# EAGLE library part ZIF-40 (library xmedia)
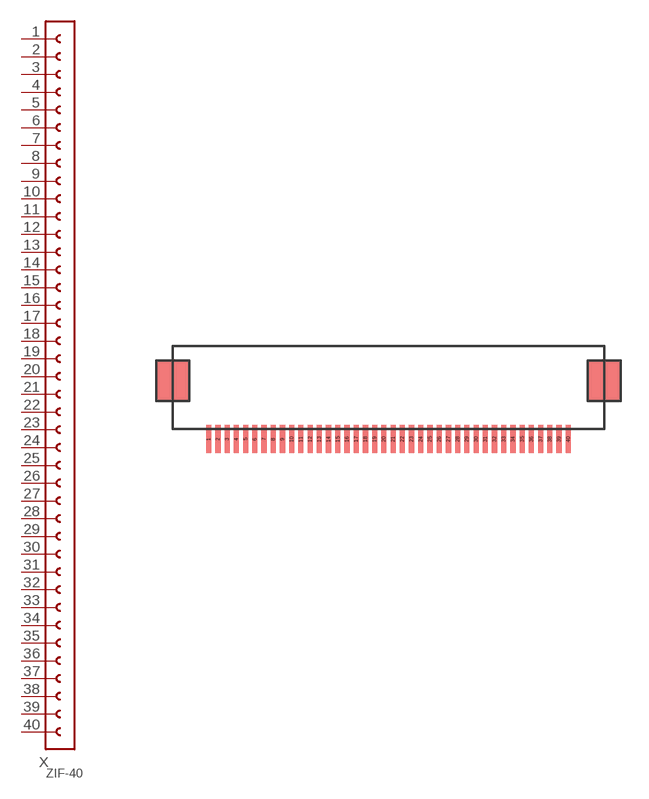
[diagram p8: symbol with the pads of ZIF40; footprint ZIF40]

Designator prefix X

## ZIF-40  [ZIF40]
1  P$1
2  P$2
3  P$3
4  P$4
5  P$5
6  P$6
7  P$7
8  P$8
9  P$9
10  P$10
11  P$11
12  P$12
13  P$13
14  P$14
15  P$15
16  P$16
17  P$17
18  P$18
19  P$19
20  P$20
21  P$21
22  P$22
23  P$23
24  P$24
25  P$25
26  P$26
27  P$27
28  P$28
29  P$29
30  P$30
31  P$31
32  P$32
33  P$33
34  P$34
35  P$35
36  P$36
37  P$37
38  P$38
39  P$39
40  P$40

## Footprint ZIF40 (pad centres in mm)
smd 0.279 x 1.524: 1 0.25,0.75; 2 0.75,0.75; 3 1.25,0.75; 4 1.75,0.75; 5 2.25,0.75; 6 2.75,0.75; 7 3.25,0.75; 8 3.75,0.75; 9 4.25,0.75; 10 4.75,0.75; 11 5.25,0.75; 12 5.75,0.75; 13 6.25,0.75; 14 6.75,0.75; 15 7.25,0.75; 16 7.75,0.75; 17 8.25,0.75; 18 8.75,0.75; 19 9.25,0.75; 20 9.75,0.75; 21 10.25,0.75; 22 10.75,0.75; 23 11.25,0.75; 24 11.75,0.75; 25 12.25,0.75; 26 12.75,0.75; 27 13.25,0.75; 28 13.75,0.75; 29 14.25,0.75; 30 14.75,0.75; 31 15.25,0.75; 32 15.75,0.75; 33 16.25,0.75; 34 16.75,0.75; 35 17.25,0.75; 36 17.75,0.75; 37 18.25,0.75; 38 18.75,0.75; 39 19.25,0.75; 40 19.75,0.75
